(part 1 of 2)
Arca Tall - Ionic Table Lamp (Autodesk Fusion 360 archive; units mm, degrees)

design "Marble Base - Ionic Table Lamp - 120V" references "Balon v2", "Chinois", "Trove - TL", "Marble Base - Silicone Gasket", "Marble Base - Plastic Insert", "Rubber Grommet", "Neoprene Pad", "2-Pole Plug End", "Arca Tall", "T9 - Bulb", "Facet Petite", "T9-5In"
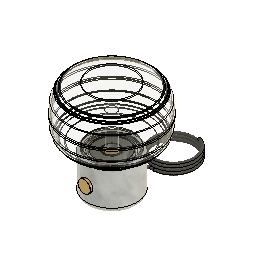
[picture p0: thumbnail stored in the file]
sketch "Sketch1" plane through (0, 0, 0) normal (0, 0, 1) x axis (1, 0, 0)
  circle C1 centre (0, 0) radius 63.5
  point P1 (0, 0)
  point P2 (0, 0)
  coincident P1 P2
extrude "Extrude1" new body sketch "Sketch1" along normal blind 101.6 bodies "Marble Base"
sketch "Sketch2" plane through (0, 0, 101.6) normal (0, 0, 1) x axis (-1, 0, 0)
  circle C1 centre (0, 0) radius 63.5
  circle C2 centre (0, 0) radius 53.975
  concentric C1 C2
  dimension "d3" diameter C2 = 107.95
extrude "Extrude2" cut sketch "Sketch2" profile of C2 against normal blind 34.925
sketch "Sketch3" plane through (0, 0, 66.675) normal (0, 0, 1) x axis (-1, 0, 0)
  circle C1 centre (0, 0) radius 53.975
  circle C2 centre (0, 0) radius 49.276
  point P1 (0, 0)
  point P3 (0, 0)
  coincident P1 P3
  dimension "d6" diameter C2 = 98.552
extrude "Extrude3" cut sketch "Sketch3" profile of C2 against normal blind 45.72
sketch "Sketch4" plane through (0, 0, 0) normal (0, 1, 0) x axis (1, 0, 0)
  circle C1 centre (0, -50.8) radius 3.81
  dimension "d9" diameter C1 = 7.62
extrude "Extrude4" cut sketch "Sketch4" against normal blind 127
sketch "Sketch5" plane through (0, 0, 0) normal (0, 1, 0) x axis (1, 0, 0)
  line L1 (0, -25.4) -> (0, 0)
  line L2 (0, -30.48) -> (0, -25.4)
  circle C1 centre (0, -30.48) radius 5.08
  point P1 (0, 0)
  point P2 (0, 0)
  point P4 (0, -30.48)
  point P5 (0, -30.48)
  coincident P1 P2
  vertical L1
  parallel L1 L2
  coincident P4 P5
  dimension "d12" diameter C1 = 10.16
extrude "Extrude5" cut sketch "Sketch5" profile of C1 along normal blind 114.3
fillet "Fillet1" radius 6.35 3.175 4.064
derived_base_feature "Derived Base Feature1" bodies "Rotary Switch"
derived_base_feature "Derived Base Feature1" bodies "Coiled - SVT (Blk Fabric)"
derived_base_feature "Derived Base Feature1" bodies "Glass Globe"
derived_base_feature "Derived Base Feature1" bodies "Metal Housing"
derived_base_feature "Derived Base Feature1" bodies "Metal Socket Cover"
derived_base_feature "Derived Base Feature1" bodies "Porcelain Socket"
derived_base_feature "Derived Base Feature1" bodies "Brass Dial - Dimmer Knob"
component_from_bodies "Body->Comp1"
offset_faces "OffsetFaces1" distance 12.7
offset_faces "OffsetFaces2" distance -12.7
derived_base_feature "Derived Base Feature1" bodies "Solitaire Petite"
move "Move1"
offset_faces "OffsetFaces1" distance 20.32
move "Move2"
extrude "Extrude6" add of existing geometry blind 25.4
offset_faces "OffsetFaces2" distance -3.81
fillet "Fillet2" radius 2.54
move "Move3"
derived_base_feature "Derived Base Feature2" bodies "Facet Petite"
move "Move4"
offset_faces "OffsetFaces1" distance 2.54
move "Move1"
derived_base_feature "Derived Base Feature1" bodies "Body1"
derived_base_feature "Derived Base Feature1" bodies "Body1"
derived_base_feature "Derived Base Feature1" bodies "Body1"
derived_base_feature "Derived Base Feature1" bodies "Body1"
derived_base_feature "Derived Base Feature1" bodies "Body1"
derived_base_feature "Derived Base Feature1" bodies "Body1", "Body2"
derived_base_feature "Derived Base Feature1" bodies "Body1"
position "Position1"
external_derived "ExternalDerived5" bodies "Plastic Insert"
derived_instance "DerivedInstance15"
offset_faces "OffsetFaces1" distance 3.81
offset_faces "OffsetFaces2" distance -1.0414
move "Move6"
external_derived "ExternalDerived6" sketch "Sketch3" bodies "Silicone Gasket"
derived_instance "DerivedInstance16"
offset_faces "OffsetFaces3" distance -10.795
move "Move1"
move_face "MoveFace1"
position "Position2"
position "Position3"
position "Position4"
position "Position5"
move "Move2"
position "Position6"
offset_faces "OffsetFaces2" distance -7.62
chamfer "Chamfer1" distance 0.381
remove_instance "RemoveInstance1"
remove_instance "RemoveInstance2"
remove_instance "RemoveInstance3"
remove_instance "RemoveInstance4"
move "Move1"
derived_base_feature "Derived Base Feature5" bodies "Oculo Petite"
align "Align1"
external_derived "ExternalDerived8"
derived_base_feature "Derived Base Feature7" bodies "Balon v2"
derived_base_feature "Derived Base Feature8" bodies "Balon v3"
align "Align3"
align "Align4"
external_derived "ExternalDerived10"
component_insert "Component Insert1"
position "Position7"
position "Position8"
derived_base_feature "Derived Base Feature11" bodies "Trove - TL"
move "Move10"
move "Move11"
remove_instance "RemoveInstance5"
split "Split1" bodies "Trove - TL (1)"
remove_body "RemoveBody2"
remove_body "RemoveBody3"
external_derived "ExternalDerived13" bodies "Trove - TL"
derived_instance "DerivedInstance20"
remove_body "RemoveBody4"
remove_body "RemoveBody5"
component_insert "Component Insert2"
component_insert "Component Insert3"
component_from_bodies "Body->Comp2"
remove_body "RemoveBody7"
move "Move12"
move "Move13"
sketch "Sketch6" plane through (0, 0, 97.917) normal (0, 0, 1) x axis (-1, 0, 0)
  circle C1 centre (0, 0) radius 41.275
  circle C2 centre (0, 0) radius 19.685
  arc A1 centre (0, 0) radius 29.3982 clockwise from (-27.6283, 10.0466) to (27.6283, 10.0466)
  arc A2 centre (0, 0) radius 26.2232 clockwise from (-24.6444, 8.9616) to (24.6444, 8.9616)
  arc A3 centre (0, 0) radius 32.5732 clockwise from (-30.6121, 11.1317) to (30.6121, 11.1317)
  arc A4 centre (0, 0) radius 35.7482 clockwise from (-33.596, 12.2167) to (33.596, 12.2167)
  point P1 (0, 0)
  point P3 (0, 0)
  coincident P1 P3
  dimension "d37" = -3.175
  dimension "d38" = 3.175
  dimension "d39" = 6.35
  dimension "d40" Text1-Height = 2.54
  dimension "d41" Text2-Height = 2.54
  dimension "d42" Text3-Height = 2.54
  dimension "d43" Text4-Height = 2.54
extrude "Extrude1" cut sketch "Sketch6" against normal blind 0.254
external_derived "ExternalDerived14" bodies "Rubber Grommet"
derived_instance "DerivedInstance19"
external_derived "ExternalDerived15" bodies "2-Pole Plug End"
derived_instance "DerivedInstance18"
external_derived "ExternalDerived16" bodies "Neoprene Pad"
derived_instance "DerivedInstance17"
position "Position9"
position "Position10"
position "Position11"
position "Position12"
external_derived "ExternalDerived17" bodies "Chinois"
derived_instance "DerivedInstance21"
position "Position13"
move "Move3"
remove_body "RemoveBody8"
component_insert "Component Insert4"
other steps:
derived_base_feature "Derived Base Feature1" bodies "Trove - TL"
derived_base_feature "Derived Base Feature1" bodies "Chinois"
derived_base_feature "Derived Base Feature1" bodies "Rubber Grommet"
derived_base_feature "Derived Base Feature1" bodies "2-Pole Plug End"
derived_base_feature "Derived Base Feature1" bodies "Neoprene Pad"
move "Move1"
base_feature "Base Feature1" bodies "Oculo Petite", "Arca Petite"
derived_base_feature "Derived Base Feature1" bodies "Plastic Insert"
derived_base_feature "Derived Base Feature1" bodies "Silicone Gasket"
base_feature "Base Feature1" bodies "Marble Base"
move "Move8"
derived_base_feature "Derived Base Feature"
create_component "CreateComponent1"
create_component "CreateComponent2"
create_component "CreateComponent3"
create_component "CreateComponent4"
create_component "CreateComponent5"
create_component "CreateComponent6"
create_component "CreateComponent7"
create_component "CreateComponent8"
remove_body "RemoveBody1"
create_component "CreateComponent9"
create_component "CreateComponent10"
create_component "CreateComponent11"
create_component "CreateComponent12"
create_component "CreateComponent13"
create_component "CreateComponent14"
create_component "CreateComponent15"
create_component "CreateComponent16"
create_component "CreateComponent17"
create_component "CreateComponent18"
remove_body "RemoveBody6"
create_component "CreateComponent19"
create_component "CreateComponent20"
create_component "CreateComponent21"
create_component "CreateComponent22"
create_component "CreateComponent23"
named bodies: "Marble Base", "Rotary Switch", "Coiled - SVT (Blk Fabric)", "Glass Globe", "Metal Housing", "Metal Socket Cover", "Porcelain Socket", "Brass Dial - Dimmer Knob", "Solitaire Petite", "Facet Petite", "Body1", "Body2", "Plastic Insert", "Silicone Gasket", "Oculo Petite", "Balon v2", "Balon v3", "Trove - TL", "Trove - TL (1)", "Arca Petite", "Neoprene Pad", "2-Pole Plug End", "Rubber Grommet", "Chinois"

design "Neoprene Pad"
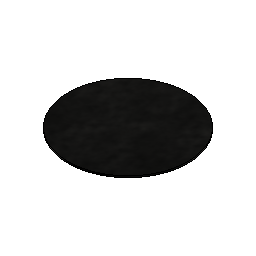
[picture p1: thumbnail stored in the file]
sketch "Sketch1" plane through (0, 0, 0) normal (0, 0, 1) x axis (1, 0, 0)
  circle C1 centre (0, 0) radius 57.15
  point P1 (0, 0)
  point P2 (0, 0)
  coincident P1 P2
extrude "Extrude1" new body sketch "Sketch1" along normal blind 1.5875 bodies "Neoprene Pad"
component_from_bodies "Body->Comp"
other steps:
base_feature "Base Feature" bodies "Neoprene Pad"
create_component "CreateComponent1"
remove_body "RemoveBody1"
named bodies: "Neoprene Pad"

design "T9 - Bulb"
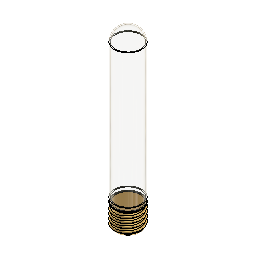
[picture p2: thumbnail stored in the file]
sketch "Sketch1" plane through (0, 0, 0) normal (0, 1, 0) x axis (1, 0, 0)
  line L1 (0, -166.37) -> (0, 0)
  line L2 (13.97, -13.97) -> (13.97, -152.4)
  line L3 (-13.97, -152.4) -> (-13.97, -13.97)
  line L4 (0, 0) -> (0, -166.37)
  line L5 (12.97, -13.97) -> (12.97, -152.4)
  line L6 (-12.97, -152.4) -> (-12.97, -13.97)
  line L7 (-12.3978, -10.16) -> (-13.4404, -10.16)
  line L8 (13.4404, -10.16) -> (12.3978, -10.16)
  arc A1 centre (0, -152.4) radius 13.97 clockwise from (13.97, -152.4) to (-13.97, -152.4)
  arc A2 centre (0, -152.4) radius 12.97 clockwise from (12.97, -152.4) to (-12.97, -152.4)
  arc A3 centre (0, -13.97) radius 13.97 clockwise from (13.4404, -10.16) to (13.97, -13.97)
  arc A4 centre (0, -13.97) radius 13.97 clockwise from (-13.97, -13.97) to (-13.4404, -10.16)
  arc A5 centre (0, -13.97) radius 12.97 clockwise from (12.3978, -10.16) to (12.97, -13.97)
  arc A6 centre (0, -13.97) radius 12.97 clockwise from (-12.97, -13.97) to (-12.3978, -10.16)
  point P1 (0, 0)
  point P2 (0, 0)
  point P3 (0, -166.37)
  point P10 (0, 0)
  point P17 (13.4404, -10.16)
  point P19 (12.3978, -10.16)
  point P4 (13.97, -152.4)
  point P5 (13.97, -13.97)
  coincident P1 P2
  vertical L1
  tangent L2 A3
  tangent L3 A3
  parallel L2 L3
  tangent L3 A1
  tangent L2 A1
  midpoint P3 A1
  coincident P1 P10
  perpendicular L1 L7
  coincident P17 L7
  concentric A3 A4
  coincident P10 A3
  concentric A1 A2
  tangent L5 A2
  tangent L5 A5
  tangent L6 A5
  tangent L6 A2
  coincident P19 L7
  concentric A5 A6
  collinear L7 L8
  dimension "d6" distance L2 L3 = 27.94
  dimension "d7" distance P4 P5 = 138.43
revolve "Revolve1" sketch "Sketch1" AlongAngle 360 bodies "T9"
derived_base_feature "Derived Base Feature" bodies "E26 Base"
align "Align1"
move "Move1"
component_from_bodies "Body->Comp1"
component_from_bodies "Body->Comp2"
copy_paste "CutPaste1"
copy_paste "CutPaste2"
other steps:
base_feature "Base Feature1" bodies "T9"
base_feature "Base Feature1" bodies "E26 Base"
create_component "CreateComponent1"
create_component "CreateComponent2"
remove_body "RemoveBody1"
create_component "CreateComponent3"
remove_body "RemoveBody2"
remove_instance "RemoveInstance1"
remove_instance "RemoveInstance2"
named bodies: "T9", "E26 Base"

design "Marble Base - Silicone Gasket"
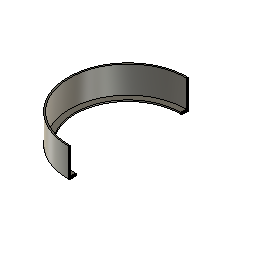
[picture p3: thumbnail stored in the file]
sketch "Sketch1" plane through (0, 0, 0) normal (0, 0, 1) x axis (1, 0, 0)
  circle C1 centre (0, 0) radius 53.34
  point P1 (0, 0)
  point P2 (0, 0)
  coincident P1 P2
extrude "Extrude1" new body sketch "Sketch1" along normal blind 25.4 bodies "Silicone Gasket"
shell "Shell1" innerThickness 1.27
sketch "Sketch2" plane through (0, 0, 1.27) normal (0, 0, 1) x axis (-1, 0, 0)
  circle C1 centre (0, 0) radius 52.07
  circle C2 centre (0, 0) radius 46.99
  concentric C1 C2
extrude "Extrude2" cut sketch "Sketch2" profile of C2 against normal blind 12.7
component_from_bodies "Body->Comp"
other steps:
base_feature "Base Feature" bodies "Silicone Gasket"
create_component "CreateComponent1"
remove_body "RemoveBody1"
named bodies: "Silicone Gasket"

design "2-Pole Plug End"
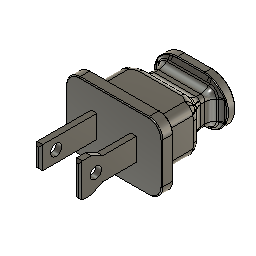
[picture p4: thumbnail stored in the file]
sketch "Sketch1" plane through (0, 0, 0) normal (0, 1, 0) x axis (1, 0, 0)
  line L1 (9.6837, 9.525) -> (-9.6837, 9.525)
  line L2 (13.4938, -5.715) -> (13.4938, 5.715)
  line L3 (-9.6837, -9.525) -> (9.6837, -9.525)
  line L4 (-13.4937, 5.715) -> (-13.4937, -5.715)
  line L5 (13.4938, -9.525) -> (-13.4937, 9.525)
  line L6 (-13.4937, -9.525) -> (13.4938, 9.525)
  arc A1 centre (-9.6837, -5.715) radius 3.81 clockwise from (-9.6837, -9.525) to (-13.4937, -5.715)
  arc A2 centre (9.6837, -5.715) radius 3.81 clockwise from (13.4938, -5.715) to (9.6837, -9.525)
  arc A3 centre (9.6837, 5.715) radius 3.81 clockwise from (9.6837, 9.525) to (13.4938, 5.715)
  arc A4 centre (-9.6837, 5.715) radius 3.81 clockwise from (-13.4937, 5.715) to (-9.6837, 9.525)
  point P6 (0, 0)
  point P1 (0, 0)
  point P5 (-13.4937, -9.525)
  point P4 (13.4938, -9.525)
  point P3 (13.4938, 9.525)
  point P2 (-13.4937, 9.525)
  horizontal L1
  perpendicular L1 L2
  parallel L1 L3
  parallel L2 L4
  coincident L5 P6
  coincident L6 P6
  coincident P1 P6
  coincident P5 L4
  coincident P5 L3
  tangent L4 A1
  tangent L3 A1
  coincident P4 L3
  coincident P4 L2
  tangent L3 A2
  tangent L2 A2
  equal A1 A2
  coincident P3 L2
  coincident P3 L1
  tangent L2 A3
  tangent L1 A3
  equal A1 A3
  coincident P2 L1
  coincident P2 L4
  tangent L1 A4
  tangent L4 A4
  equal A1 A4
  dimension "d1" distance P4 P5 = 26.9875
  dimension "d2" distance P2 P5 = 19.05
  dimension "d3" radius A1 = 3.81
extrude "Extrude1" new body sketch "Sketch1" profile of L1 L2 L3 L4 A1 A2 A3 A4 along normal blind 3.175
sketch "Sketch2" plane through (0, 3.175, 0) normal (0, 1, 0) x axis (-1, 0, 0)
  line L1 (9.6837, -9.525) -> (-9.6837, -9.525)
  line L2 (13.4937, 5.715) -> (13.4937, -5.715)
  line L3 (-9.6837, 9.525) -> (9.6837, 9.525)
  line L4 (-13.4938, -5.715) -> (-13.4938, 5.715)
  line L5 (10.16, -6.35) -> (-10.16, -6.35)
  line L6 (10.16, 6.35) -> (10.16, -6.35)
  line L7 (-10.16, 6.35) -> (10.16, 6.35)
  line L8 (-10.16, -6.35) -> (-10.16, 6.35)
  line L9 (10.16, 6.35) -> (-10.16, -6.35)
  line L10 (-10.16, 6.35) -> (10.16, -6.35)
  arc A1 centre (-9.6837, -5.715) radius 3.81 clockwise from (-9.6837, -9.525) to (-13.4938, -5.715)
  arc A2 centre (9.6837, -5.715) radius 3.81 clockwise from (13.4937, -5.715) to (9.6837, -9.525)
  arc A3 centre (9.6837, 5.715) radius 3.81 clockwise from (9.6837, 9.525) to (13.4937, 5.715)
  arc A4 centre (-9.6837, 5.715) radius 3.81 clockwise from (-13.4938, 5.715) to (-9.6837, 9.525)
  point P18 (0, 0)
  point P1 (0, 0)
  horizontal L5
  perpendicular L5 L6
  parallel L5 L7
  parallel L6 L8
  coincident L9 P18
  coincident L10 P18
  coincident P1 P18
extrude "Extrude2" add sketch "Sketch2" profile of L5 L6 L7 L8 along normal blind 9.525
sketch "Sketch3" plane through (0, 12.7, 0) normal (0, 1, 0) x axis (-1, 0, 0)
  line L1 (-10.16, -6.35) -> (-10.16, 6.35)
  line L2 (10.16, -6.35) -> (-10.16, -6.35)
  line L3 (10.16, 6.35) -> (10.16, -6.35)
  line L4 (-10.16, 6.35) -> (10.16, 6.35)
  line L5 (-7.1437, 3.9688) -> (7.1437, 3.9688)
  line L6 (-7.1437, -3.9688) -> (-7.1437, 3.9688)
  line L7 (7.1437, -3.9688) -> (-7.1437, -3.9688)
  line L8 (7.1437, 3.9688) -> (7.1437, -3.9688)
  line L9 (-7.1437, -3.9688) -> (7.1437, 3.9688)
  line L10 (7.1437, -3.9688) -> (-7.1437, 3.9688)
  point P10 (0, 0)
  point P1 (0, 0)
  point P8 (-7.1437, -3.9688)
  point P9 (7.1437, -3.9688)
  point P7 (-7.1437, 3.9688)
  horizontal L5
  perpendicular L5 L6
  parallel L5 L7
  parallel L6 L8
  coincident L9 P10
  coincident L10 P10
  coincident P1 P10
  dimension "d8" distance P8 P9 = 14.2875
  dimension "d9" distance P7 P8 = 7.9375
extrude "Extrude3" add sketch "Sketch3" profile of L5 L6 L7 L8 along normal blind 11.1125
fillet "Fillet1" radius 2.286 1.27 0.254
chamfer "Chamfer1" distance 3.429
fillet "Fillet2" radius 2.54 1.905
sketch "Sketch4" plane through (0, 23.8125, 0) normal (0, 1, 0) x axis (-1, 0, 0)
  line L1 (-7.1437, -2.6987) -> (-7.1437, 2.6987)
  line L2 (5.8737, -3.9688) -> (-5.8737, -3.9688)
  line L3 (7.1437, 2.6987) -> (7.1437, -2.6987)
  line L4 (-5.8737, 3.9688) -> (5.8737, 3.9688)
  line L5 (-3.81, 6.604) -> (3.81, 6.604)
  line L6 (3.81, -6.604) -> (-3.81, -6.604)
  line L7 (-10.414, 0) -> (10.414, 0)
  arc A1 centre (-5.8737, 2.6987) radius 1.27 clockwise from (-7.1437, 2.6987) to (-5.8737, 3.9688)
  arc A2 centre (-5.8737, -2.6987) radius 1.27 clockwise from (-5.8737, -3.9688) to (-7.1437, -2.6987)
  arc A3 centre (5.8737, -2.6987) radius 1.27 clockwise from (7.1437, -2.6987) to (5.8737, -3.9688)
  arc A4 centre (5.8737, 2.6987) radius 1.27 clockwise from (5.8737, 3.9688) to (7.1437, 2.6987)
  arc A5 centre (-3.81, 0) radius 6.604 clockwise from (-3.81, -6.604) to (-3.81, 6.604)
  arc A6 centre (3.81, 0) radius 6.604 clockwise from (3.81, 6.604) to (3.81, -6.604)
  point P20 (10.414, 0)
  point P21 (-10.414, 0)
  tangent L5 A5
  tangent A5 L6
  parallel L5 L6
  tangent L6 A6
  tangent L5 A6
  midpoint A6 P20
  midpoint A5 P21
  perpendicular L1 L7
extrude "Extrude4" add sketch "Sketch4" profile of A1 L1 A2 L2 A3 L3 A4 L4 L5 A5 L6 A6 against normal blind 2.286
chamfer "Chamfer2" distance 1.778
fillet "Fillet3" radius 1.778
fillet "Fillet4" radius 0.254
fillet "Fillet5" radius 0.254
fillet "Fillet6" radius 0.254
fillet "Fillet7" radius 3.175
sketch "Sketch5" plane through (0, 0, 0) normal (0, -1, 0) x axis (1, 0, 0)
  line L1 (-13.2397, -5.715) -> (-13.2397, 5.715)
  line L2 (9.6837, -9.271) -> (-9.6837, -9.271)
  line L3 (13.2397, 5.715) -> (13.2397, -5.715)
  line L4 (-9.6837, 9.271) -> (9.6837, 9.271)
  line L5 (-6.35, -3.175) -> (-6.35, 3.175)
  line L6 (6.35, 3.175) -> (-6.35, -3.175)
  line L7 (-6.35, 3.175) -> (6.35, -3.175)
  line L8 (-4.7625, 3.175) -> (-6.35, 3.175)
  line L9 (-4.7625, -3.175) -> (-4.7625, 3.175)
  line L10 (-6.35, -3.175) -> (-4.7625, -3.175)
  line L11 (-6.35, 3.175) -> (-6.35, -3.175)
  line L12 (0, -3.302) -> (0, 3.81)
  line L13 (4.7625, -3.175) -> (4.7625, 3.175)
  line L14 (4.7625, 3.175) -> (6.35, 3.175)
  line L15 (6.35, -3.175) -> (6.35, 3.175)
  line L16 (6.35, -3.175) -> (4.7625, -3.175)
  arc A1 centre (-9.6837, 5.715) radius 3.556 clockwise from (-13.2397, 5.715) to (-9.6837, 9.271)
  arc A2 centre (-9.6837, -5.715) radius 3.556 clockwise from (-9.6837, -9.271) to (-13.2397, -5.715)
  arc A3 centre (9.6837, -5.715) radius 3.556 clockwise from (13.2397, -5.715) to (9.6837, -9.271)
  arc A4 centre (9.6837, 5.715) radius 3.556 clockwise from (9.6837, 9.271) to (13.2397, 5.715)
  point P18 (0, 0)
  point P1 (0, 0)
  point P14 (-6.35, -3.175)
  point P27 (6.35, -3.175)
  point P17 (-6.35, 3.175)
  point P26 (6.35, 3.175)
  point P19 (-4.7625, 3.175)
  point P24 (4.7625, 3.175)
  point P20 (-4.7625, -3.175)
  point P25 (4.7625, -3.175)
  point P21 (-6.35, -3.175)
  point P28 (6.35, -3.175)
  point P15 (6.35, -3.175)
  point P16 (6.35, 3.175)
  coincident L6 P18
  coincident L7 P18
  coincident P1 P18
  horizontal L8
  vertical L9
  horizontal L10
  vertical L11
  vertical L12
  symmetric P14 L12 P27
  symmetric P17 L12 P26
  symmetric P19 L12 P24
  symmetric P20 L12 P25
  symmetric P21 L12 P28
  dimension "d36" distance P15 P16 = 6.35
  dimension "d37" distance P17 P19 = 1.5875
extrude "Extrude5" add sketch "Sketch5" profile of L5 L8 L9 L10 L11 L13 L14 L15 L16 along normal blind 15.875
sketch "Sketch7" plane through (0, 0, 3.175) normal (0, 0, 1) x axis (-1, 0, 0)
  line L1 (-4.7625, 0) -> (-6.35, 0)
  line L2 (-4.7625, 15.875) -> (-4.7625, 0)
  line L3 (-6.35, 15.875) -> (-4.7625, 15.875)
  line L4 (-6.35, 0) -> (-6.35, 15.875)
  line L5 (-4.7625, 15.875) -> (-6.35, 15.875)
  line L6 (-4.7625, 9.525) -> (-4.7625, 15.875)
  line L7 (-6.35, 9.525) -> (-4.7625, 9.525)
  line L8 (-6.35, 15.875) -> (-6.35, 9.525)
  point P5 (-6.35, 15.875)
  point P6 (-6.35, 15.875)
  point P9 (-6.35, 9.525)
  horizontal L5
  vertical L6
  horizontal L7
  vertical L8
  coincident P5 P6
  dimension "d45" distance P6 P9 = 6.35
extrude "Extrude7" add sketch "Sketch7" profile of L2 L3 L4 L5 L6 L7 L8 against normal blind 7.9375 and along normal blind 1.5875
chamfer "Chamfer3" distance 0.508
chamfer "Chamfer4" distance 0.635 distance 0.635
sketch "Sketch6" plane through (6.35, 0, 0) normal (1, 0, 0) x axis (0, 1, 0)
  line L1 (0, -3.175) -> (-9.525, -3.175)
  line L2 (0, 3.175) -> (0, -3.175)
  line L3 (-9.525, 3.175) -> (0, 3.175)
  line L4 (-15.367, -4.6355) -> (-15.367, 4.6355)
  line L5 (-11.43, 0) -> (-16.002, 0)
  line L6 (-9.525, -4.7625) -> (-15.24, -4.7625)
  line L7 (-9.525, -3.175) -> (-9.525, -4.7625)
  line L8 (-9.525, 4.7625) -> (-9.525, 3.175)
  line L9 (-15.24, 4.7625) -> (-9.525, 4.7625)
  line L10 (-15.24, -4.7625) -> (-15.367, -4.6355)
  line L11 (-15.367, 4.6355) -> (-15.24, 4.7625)
  circle C1 centre (-11.43, 0) radius 1.5875
  point P9 (-11.43, 0)
  point P10 (-11.43, 0)
  perpendicular L4 L5
  coincident P9 P10
  dimension "d42" diameter C1 = 3.175
extrude "Extrude6" cut sketch "Sketch6" profile of C1 against normal blind 20.32
chamfer "Chamfer5" distance 3.175 distance 1.5875 distance 3.175 distance 1.5875
component_from_bodies "Body->Comp"
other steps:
base_feature "Base Feature" bodies "2-Pole Plug End"
create_component "CreateComponent1"
remove_body "RemoveBody1"
named bodies: "2-Pole Plug End"

design "Facet Petite"
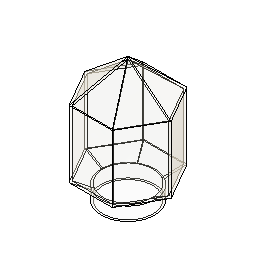
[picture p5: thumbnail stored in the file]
sketch "Sketch7" plane through (0, 0, 0) normal (1, 0, 0) x axis (0, 1, 0)
sketch "Sketch8" plane through (0, 0, 0) normal (0, 0, 1) x axis (1, 0, 0)
  circle C1 centre (0, 0) radius 50.8
  point P1 (0, 0)
  point P2 (0, 0)
  coincident P1 P2
  dimension "d17" diameter C1 = 101.6
extrude "Extrude5" new body sketch "Sketch8" along normal blind 25.4 and against normal blind 25.4
work_plane "WorkPlane1" AlongDistance 17.78
sketch "Sketch10" plane through (0, 0, 25.4) normal (0, 0, 1) x axis (-1, 0, 0)
  circle C1 centre (0, 0) radius 50.8
sketch "Sketch12" plane through (0, 0, 43.18) normal (0, 0, 1) x axis (1, 0, 0)
  line L1 (-82.1223, 0) -> (-41.0612, 71.12)
  line L2 (-41.0612, -71.12) -> (-82.1223, 0)
  line L3 (41.0612, -71.12) -> (-41.0612, -71.12)
  line L4 (82.1223, 0) -> (41.0612, -71.12)
  line L5 (41.0612, 71.12) -> (82.1223, 0)
  line L6 (-41.0612, 71.12) -> (41.0612, 71.12)
  point P1 (0, 0)
  point P8 (0, 0)
  coincident P1 P8
  dimension "d22" distance P8 L6 = 71.12
sketch "Sketch15" plane through (0, 0, 0) normal (0, 1, 0) x axis (1, 0, 0)
  line L1 (53.7365, -21.6801) -> (82.1223, -43.18)
  line L2 (-50.8, -25.4) -> (-82.1223, -43.18)
  point P2 (82.1223, -43.18)
  point P3 (82.1223, -43.18)
  point P5 (-82.1223, -43.18)
  point P7 (-82.1223, -43.18)
  point P6 (-50.8, -25.4)
  point P8 (-50.8, -25.4)
  coincident P2 P3
  coincident P5 P7
  coincident P6 P8
sketch "Sketch17" plane through (0, 0, 25.4) normal (0, 0, 1) x axis (-1, 0, 0)
  line L1 (51.3255, 0) -> (0, 0)
  line L2 (73.3235, 0) -> (0, 0)
  line L3 (-41.0612, -71.12) -> (-25.4, -43.9941)
  line L4 (-36.6617, -63.5) -> (-25.4, -43.9941)
  line L5 (78.4305, 0) -> (0, 0)
  line L6 (41.0612, -71.12) -> (25.4, -43.9941)
  line L7 (25.4, 43.9941) -> (41.0612, 71.12)
  line L8 (73.3235, 0) -> (0, 0)
  line L9 (-25.4, 43.9941) -> (-41.0612, 71.12)
  line L10 (0, 0) -> (0, 0)
  circle C1 centre (0, 0) radius 50.8
  point P1 (0, 0)
  point P4 (0, 0)
  point P2 (-41.0612, -71.12)
  point P6 (-41.0612, -71.12)
  point P3 (0, 0)
  point P7 (0, 0)
  point P9 (-25.4, -43.9941)
  point P12 (41.0612, -71.12)
  point P13 (41.0612, -71.12)
  point P15 (25.4, -43.9941)
  point P16 (41.0612, 71.12)
  point P17 (41.0612, 71.12)
  point P18 (25.4, 43.9941)
  point P19 (-41.0612, 71.12)
  point P20 (-41.0612, 71.12)
  point P21 (0, 0)
  point P23 (-25.4, 43.9941)
  point P25 (0, 0)
  point P24 (0, 0)
  point P26 (0, 0)
  horizontal L1
  coincident P1 P4
  coincident P2 P6
  horizontal L2
  coincident P3 P7
  coincident C1 P9
  coincident P12 P13
  horizontal L5
  coincident C1 P15
  coincident P16 P17
  coincident C1 P18
  coincident P19 P20
  horizontal L8
  coincident P1 P21
  coincident C1 P23
  coincident P1 P25
  coincident P24 P26
extrude "Extrude6" new body sketch "Sketch12" along normal blind 127
work_plane "WorkPlane2" AlongDistance 66.04
sketch "Sketch18" plane through (0, 0, 236.22) normal (0, 0, 1) x axis (1, 0, 0)
  line L1 (41.0612, -71.12) -> (0, 0)
  line L2 (82.1223, 0) -> (0, 0)
  line L3 (41.0612, 71.12) -> (0, 0)
  line L4 (-41.0612, 71.12) -> (0, 0)
  line L5 (-82.1223, 0) -> (0, 0)
  line L6 (-41.0612, -71.12) -> (0, 0)
  point P1 (0, 0)
  point P3 (0, 0)
  point P2 (41.0612, -71.12)
  point P4 (41.0612, -71.12)
  point P6 (0, 0)
  point P5 (82.1223, 0)
  point P7 (82.1223, 0)
  point P9 (0, 0)
  point P8 (41.0612, 71.12)
  point P10 (41.0612, 71.12)
  point P12 (0, 0)
  point P11 (-41.0612, 71.12)
  point P13 (-41.0612, 71.12)
  point P15 (0, 0)
  point P14 (-82.1223, 0)
  point P16 (-82.1223, 0)
  point P18 (0, 0)
  point P17 (-41.0612, -71.12)
  point P19 (-41.0612, -71.12)
  coincident P1 P3
  coincident P2 P4
  coincident P1 P6
  coincident P5 P7
  coincident P1 P9
  coincident P8 P10
  coincident P1 P12
  coincident P11 P13
  coincident P1 P15
  coincident P14 P16
  coincident P1 P18
  coincident P17 P19
loft "Loft1"
loft "Loft2" sketch "Sketch17"
component_from_bodies "Body->Comp"
extrude "Extrude1" cut of existing geometry blind -25.4
shell "Shell2" innerThickness 3.81
fillet "Fillet1" radius 7.62
fillet "Fillet2" radius 6.35
fillet "Fillet3" radius 6.35
fillet "Fillet4" radius 6.35
fillet "Fillet5" radius 6.35
fillet "Fillet6" radius 6.35
fillet "Fillet7" radius 3.81
fillet "Fillet8" radius 6.35
fillet "Fillet9" radius 6.35
fillet "Fillet10" radius 6.35
fillet "Fillet11" radius 6.35
fillet "Fillet12" radius 6.35
fillet "Fillet13" radius 2.286
shell "Shell1" innerThickness 2.54
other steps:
base_feature "Base Feature"
create_component "CreateComponent3"
remove_body "RemoveBody2"

design "Chinois"
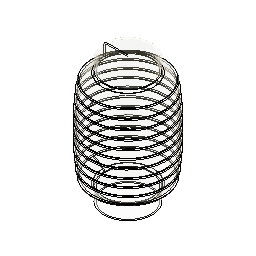
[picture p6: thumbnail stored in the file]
named bodies: "Chinois"

design "Marble Base - Plastic Insert"
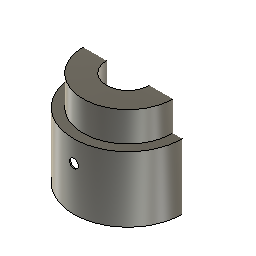
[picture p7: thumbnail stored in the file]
sketch "Sketch1" plane through (0, 0, 0) normal (0, 0, 1) x axis (1, 0, 0)
  circle C1 centre (0, 0) radius 50.038
  point P1 (0, 0)
  point P2 (0, 0)
  coincident P1 P2
  dimension "d1" diameter C1 = 100.076
extrude "Extrude1" new body sketch "Sketch1" along normal blind 72.898 bodies "Plastic Insert"
shell "Shell1" innerThickness 1.016
work_plane "WorkPlane1" AlongDistance 18.034
sketch "Sketch2" plane through (0, 0, 90.932) normal (0, 0, 1) x axis (1, 0, 0)
  circle C1 centre (0, 0) radius 20.701
  point P1 (0, 0)
  point P2 (0, 0)
  coincident P1 P2
  dimension "d6" diameter C1 = 41.402
extrude "Extrude2" add sketch "Sketch2" against normal blind 65.024
shell "Shell2" innerThickness 1.016
sketch "Sketch3" plane through (0, 0, 0) normal (0, 1, 0) x axis (1, 0, 0)
  line L1 (5.08, -20.32) -> (-5.08, -20.32)
  line L2 (5.08, 20.32) -> (5.08, -20.32)
  line L3 (-5.08, 20.32) -> (5.08, 20.32)
  line L4 (-5.08, -20.32) -> (-5.08, 20.32)
  line L5 (5.08, 20.32) -> (-5.08, -20.32)
  line L6 (-5.08, 20.32) -> (5.08, -20.32)
  point P6 (0, 0)
  point P1 (0, 0)
  horizontal L1
  perpendicular L1 L2
  parallel L1 L3
  parallel L2 L4
  coincident L5 P6
  coincident L6 P6
  coincident P1 P6
extrude "Extrude3" cut sketch "Sketch3" profile of L1 L2 L3 L4 along normal blind 91.44
sketch "Sketch4" plane through (0, 0, 0) normal (0, 1, 0) x axis (1, 0, 0)
  line L1 (0, -40.64) -> (0, 0)
  circle C1 centre (0, -40.64) radius 4.064
  point P1 (0, 0)
  point P2 (0, 0)
  point P3 (0, -40.64)
  point P4 (0, -40.64)
  coincident P1 P2
  vertical L1
  coincident P3 P4
  dimension "d12" diameter C1 = 8.128
work_plane "WorkPlane2" AlongDistance -91.44
sketch "Sketch5" plane through (0, -91.44, 0) normal (0, 1, 0) x axis (1, 0, 0)
  circle C1 centre (0, -40.64) radius 4.064
extrude "Extrude4" cut sketch "Sketch5" along normal blind 63.5
sketch "Sketch6" plane through (0, 0, 26.924) normal (0, 0, 1) x axis (-1, 0, 0)
  circle C1 centre (0, 0) radius 19.685
  circle C2 centre (0, 0) radius 5.461
  concentric C1 C2
  dimension "d16" diameter C2 = 10.922
extrude "Extrude5" cut sketch "Sketch6" profile of C2 against normal blind 15.24
sketch "Sketch7" plane through (0, 0, 72.898) normal (0, 0, 1) x axis (-1, 0, 0)
  circle C1 centre (0, 0) radius 20.701
  circle C2 centre (0, 0) radius 50.038
  circle C3 centre (0, 0) radius 20.701
  circle C4 centre (0, 0) radius 45.72
  point P1 (0, 0)
  point P3 (0, 0)
  point P4 (0, 0)
  coincident P1 P3
  coincident P1 P4
extrude "Extrude6" add sketch "Sketch7" profile of C1 C3 C4 along normal blind 18.034
sketch "Sketch8" plane through (0, 0, 71.882) normal (0, 0, -1) x axis (1, 0, 0)
  circle C1 centre (0, 0) radius 20.701
  circle C2 centre (0, 0) radius 49.022
  circle C3 centre (0, 0) radius 20.701
  circle C4 centre (0, 0) radius 44.704
  point P1 (0, 0)
  point P3 (0, 0)
  point P4 (0, 0)
  coincident P1 P3
  coincident P1 P4
  dimension "d21" diameter C4 = 89.408
extrude "Extrude7" cut sketch "Sketch8" profile of C1 C3 C4 against normal blind 17.78
extrude "Extrude8" add of existing geometry blind 9.398
extrude "Extrude9" cut of existing geometry blind -9.398
component_from_bodies "Body->Comp"
offset_faces "OffsetFaces1" distance 4.445
offset_faces "OffsetFaces2" distance -4.445
offset_faces "OffsetFaces3" distance 3.175
offset_faces "OffsetFaces4" distance 3.175
offset_faces "OffsetFaces5" distance 3.175
offset_faces "OffsetFaces6" distance -3.175
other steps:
base_feature "Base Feature" bodies "Plastic Insert"
create_component "CreateComponent1"
remove_body "RemoveBody1"
named bodies: "Plastic Insert"

design "Arca Tall"
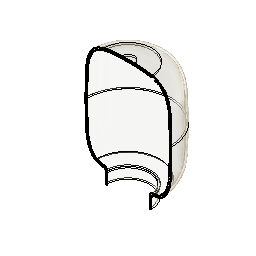
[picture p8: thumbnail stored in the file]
derived_base_feature "Derived Base Feature" bodies "Balon"
work_plane "WorkPlane1" AlongDistance 0
sketch "Sketch1" plane through (0, 0, 0) normal (0, 1, 0) x axis (1, 0, 0)
  line L1 (0, 317.5) -> (0, 2.9083)
  curve K1 (-82.9821, 124.2212) -> (-50.8, 237.8015)
  curve K2 (-51.0925, 237.681) -> (-50.8, 237.8015)
  curve K3 (-51.3855, 237.5558) -> (-51.0925, 237.681)
  curve K4 (-54.7608, 236.0513) -> (-51.3855, 237.5558)
  curve K5 (-57.9615, 234.05) -> (-54.7608, 236.0513)
  curve K6 (-67.2727, 226.749) -> (-57.9615, 234.05)
  curve K7 (-69.0552, 224.2615) -> (-67.2727, 226.749)
  curve K8 (-72.1872, 218.7832) -> (-69.0552, 224.2615)
  curve K9 (-74.1213, 215.1556) -> (-72.1872, 218.7832)
  curve K10 (-78.3031, 204.3965) -> (-74.1213, 215.1556)
  curve K11 (-79.7275, 197.3397) -> (-78.3031, 204.3965)
  curve K12 (-81.3333, 185.4664) -> (-79.7275, 197.3397)
  curve K13 (-81.6254, 178.4008) -> (-81.3333, 185.4664)
  curve K14 (-82.49, 152.2133) -> (-81.6254, 178.4008)
  curve K15 (-82.9821, 136.067) -> (-82.49, 152.2133)
  curve K16 (-82.9821, 124.2212) -> (-82.9821, 136.067)
  curve K17 (50.8, 237.7999) -> (82.9821, 124.2212)
  curve K18 (82.9821, 140.3031) -> (82.9821, 124.2212)
  curve K19 (81.9353, 169.4257) -> (82.9821, 140.3031)
  curve K20 (81.3621, 183.6489) -> (81.9353, 169.4257)
  curve K21 (80.9478, 189.8724) -> (81.3621, 183.6489)
  curve K22 (77.8147, 206.9858) -> (80.9478, 189.8724)
  curve K23 (74.9652, 213.2153) -> (77.8147, 206.9858)
  curve K24 (69.4688, 224.1531) -> (74.9652, 213.2153)
  curve K25 (67.2512, 226.458) -> (69.4688, 224.1531)
  curve K26 (61.5696, 231.3138) -> (67.2512, 226.458)
  curve K27 (57.377, 234.6711) -> (61.5696, 231.3138)
  curve K28 (52.0556, 237.2628) -> (57.377, 234.6711)
  curve K29 (51.4313, 237.5413) -> (52.0556, 237.2628)
  curve K30 (50.8, 237.7999) -> (51.4313, 237.5413)
  line L2 (-50.8, 317.5) -> (-50.8, 237.8015)
  line L3 (50.8, 317.5) -> (50.8, 237.7999)
  line L4 (-19.0713, 6.7501) -> (-19.0713, 6.7501)
  curve K31 (82.9821, 124.1958) -> (40.1509, 7.3012)
  curve K32 (41.8198, 7.6176) -> (40.1509, 7.3012)
  curve K33 (43.2113, 8.0663) -> (41.8198, 7.6176)
  curve K34 (47.0139, 9.2854) -> (43.2113, 8.0663)
  curve K35 (47.3314, 9.3805) -> (47.0139, 9.2854)
  curve K36 (50.1192, 10.3272) -> (47.3314, 9.3805)
  curve K37 (51.833, 11.0085) -> (50.1192, 10.3272)
  curve K38 (57.8313, 14.1895) -> (51.833, 11.0085)
  curve K39 (61.4491, 17.0488) -> (57.8313, 14.1895)
  curve K40 (66.8203, 21.5867) -> (61.4491, 17.0488)
  curve K41 (68.5372, 23.5528) -> (66.8203, 21.5867)
  curve K42 (71.2201, 27.8971) -> (68.5372, 23.5528)
  curve K43 (74.7424, 33.8984) -> (71.2201, 27.8971)
  curve K44 (78.2342, 44.8406) -> (74.7424, 33.8984)
  curve K45 (79.6792, 50.3463) -> (78.2342, 44.8406)
  curve K46 (81.3558, 63.5576) -> (79.6792, 50.3463)
  curve K47 (81.6386, 70.4415) -> (81.3558, 63.5576)
  curve K48 (82.4897, 96.2198) -> (81.6386, 70.4415)
  curve K49 (82.9814, 112.3523) -> (82.4897, 96.2198)
  curve K50 (82.9821, 124.1958) -> (82.9814, 112.3523)
  curve K51 (-40.1501, 7.301) -> (-82.9821, 124.1958)
  curve K52 (-82.9813, 110.5256) -> (-82.9821, 124.1958)
  curve K53 (-82.2545, 88.8594) -> (-82.9813, 110.5256)
  curve K54 (-81.6277, 70.519) -> (-82.2545, 88.8594)
  curve K55 (-81.3572, 64.3441) -> (-81.6277, 70.519)
  curve K56 (-79.4149, 46.8924) -> (-81.3572, 64.3441)
  curve K57 (-76.5204, 38.9768) -> (-79.4149, 46.8924)
  curve K58 (-73.5142, 32.2947) -> (-76.5204, 38.9768)
  curve K59 (-72.5556, 30.3818) -> (-73.5142, 32.2947)
  curve K60 (-69.7914, 25.3691) -> (-72.5556, 30.3818)
  curve K61 (-68.3824, 23.4028) -> (-69.7914, 25.3691)
  curve K62 (-64.5419, 19.5456) -> (-68.3824, 23.4028)
  curve K63 (-62.3002, 17.7646) -> (-64.5419, 19.5456)
  curve K64 (-53.6583, 11.1976) -> (-62.3002, 17.7646)
  curve K65 (-49.6968, 10.1396) -> (-53.6583, 11.1976)
  curve K66 (-43.4141, 8.1331) -> (-49.6968, 10.1396)
  curve K67 (-41.9704, 7.6516) -> (-43.4141, 8.1331)
  curve K68 (-40.1963, 7.3098) -> (-41.9704, 7.6516)
  curve K69 (-40.1732, 7.3054) -> (-40.1963, 7.3098)
  curve K70 (-40.1501, 7.301) -> (-40.1732, 7.3054)
  line L5 (-82.9821, 124.1958) -> (-82.9821, 124.2212)
  line L6 (82.9821, 124.2212) -> (82.9821, 124.1958)
  line L7 (0, 317.5) -> (-50.8, 317.5)
  line L8 (7.2015, 3.048) -> (0, 3.048)
  line L9 (0, 3.048) -> (-7.2015, 3.048)
  arc A1 centre (0, 188.595) radius 185.6867 clockwise from (-7.2015, 3.048) to (-40.1502, 7.301)
  arc A2 centre (0, 188.595) radius 185.6867 clockwise from (40.151, 7.3012) to (7.2015, 3.048)
  point P38 (-40.1502, 7.301)
  point P43 (40.1509, 7.3012)
  point P62 (-40.1501, 7.301)
  point P81 (40.151, 7.3012)
  point P84 (0, 3.048)
  vertical L1
  horizontal L4
  coincident P38 K51
  symmetric L1 A1 A2
  coincident A2 P43
  coincident A1 P62
  coincident K31 P81
  perpendicular L2 L7
  horizontal L8
  coincident L1 P84
  horizontal L9
revolve "Revolve1" sketch "Sketch1" AlongAngle 360
shell "Shell1" innerThickness 3.81
fillet "Fillet1" radius 6.35 bodies "Balon v3"
offset_faces "OffsetFaces1" distance -50.8
move "Move1"
move "Move2"
component_from_bodies "Body->Comp1"
component_from_bodies "Body->Comp2"
sketch "Sketch2" plane through (0, 0, 0) normal (0, 1, 0) x axis (1, 0, 0)
  line L1 (-85.5221, 124.2212) -> (-85.5221, 124.1961)
  curve K1 (-58.9057, 236.4383) -> (-50.8, 241.7989)
  curve K2 (-50.8, 241.554) -> (-50.8, 241.7989)
  curve K3 (-50.904, 240.933) -> (-50.8, 241.554)
  curve K4 (-51.2936, 240.2837) -> (-50.904, 240.933)
  curve K5 (-51.734, 239.7561) -> (-51.2936, 240.2837)
  curve K6 (-53.328, 238.5038) -> (-51.734, 239.7561)
  curve K7 (-54.0892, 238.1997) -> (-53.328, 238.5038)
  curve K8 (-58.9057, 236.4383) -> (-54.0892, 238.1997)
  curve K9 (-89.3309, 124.2212) -> (-58.9057, 236.4383)
  curve K10 (-62.6336, 234.9735) -> (-58.9057, 236.4383)
  curve K11 (-65.581, 233.1032) -> (-62.6336, 234.9735)
  curve K12 (-73.0224, 227.0019) -> (-65.581, 233.1032)
  curve K13 (-74.8981, 224.836) -> (-73.0224, 227.0019)
  curve K14 (-78.1104, 219.6097) -> (-74.8981, 224.836)
  curve K15 (-80.2663, 215.561) -> (-78.1104, 219.6097)
  curve K16 (-84.0943, 205.8277) -> (-80.2663, 215.561)
  curve K17 (-85.4655, 200.1154) -> (-84.0943, 205.8277)
  curve K18 (-87.4092, 188.5789) -> (-85.4655, 200.1154)
  curve K19 (-87.7349, 182.3889) -> (-87.4092, 188.5789)
  curve K20 (-88.4233, 165.9645) -> (-87.7349, 182.3889)
  curve K21 (-89.328, 138.6964) -> (-88.4233, 165.9645)
  curve K22 (-89.3309, 124.2212) -> (-89.328, 138.6964)
  line L2 (-89.3309, 124.1958) -> (-89.3309, 124.2212)
  curve K23 (-46.5001, 7.301) -> (-89.3309, 124.1958)
  curve K24 (-89.3314, 112.4293) -> (-89.3309, 124.1958)
  curve K25 (-88.8181, 95.3068) -> (-89.3314, 112.4293)
  curve K26 (-88.346, 81.2892) -> (-88.8181, 95.3068)
  curve K27 (-88.0298, 70.4902) -> (-88.346, 81.2892)
  curve K28 (-87.1514, 58.328) -> (-88.0298, 70.4902)
  curve K29 (-86.3326, 50.6119) -> (-87.1514, 58.328)
  curve K30 (-81.0932, 33.6688) -> (-86.3326, 50.6119)
  curve K31 (-77.3163, 27.4309) -> (-81.0932, 33.6688)
  curve K32 (-74.8955, 23.6666) -> (-77.3163, 27.4309)
  curve K33 (-73.5108, 22.0741) -> (-74.8955, 23.6666)
  curve K34 (-70.2346, 19.0457) -> (-73.5108, 22.0741)
  curve K35 (-64.8094, 14.3548) -> (-70.2346, 19.0457)
  curve K36 (-56.6696, 10.3041) -> (-64.8094, 14.3548)
  curve K37 (-54.0053, 9.483) -> (-56.6696, 10.3041)
  curve K38 (-49.1487, 7.9411) -> (-54.0053, 9.483)
  curve K39 (-48.3482, 7.6526) -> (-49.1487, 7.9411)
  curve K40 (-46.5001, 7.301) -> (-48.3482, 7.6526)
  line L3 (0, 266.7) -> (0, 0)
  line L4 (0, 3.048) -> (-7.7894, 3.048)
  line L5 (-50.8, 266.7) -> (-50.8, 241.7989)
  line L6 (0, 266.7) -> (-50.8, 266.7)
  arc A1 centre (-6.9779, 188.7329) radius 185.6867 clockwise from (-7.7894, 3.048) to (-46.5001, 7.301)
  point P1 (0, 0)
  point P44 (0, 0)
  point P46 (0, 3.048)
  point P5 (-50.8, 241.554)
  point P49 (0, 266.7)
  coincident P1 P44
  coincident L3 P46
  coincident P5 L5
  coincident L3 P49
revolve "Revolve2" sketch "Sketch2" AlongAngle 360 bodies "Balon v3"
shell "Shell2" innerThickness 3.81
component_from_bodies "Body->Comp3"
remove_instance "RemoveInstance1"
remove_instance "RemoveInstance2"
sketch "Sketch1" plane through (0, 0, 0) normal (0, 1, 0) x axis (1, 0, 0)
  line L1 (-6.35, 3.048) -> (-14.1394, 3.048)
  curve K1 (-52.8501, 7.301) -> (-95.6809, 124.1958)
  curve K2 (-95.6814, 112.4293) -> (-95.6809, 124.1958)
  curve K3 (-95.1681, 95.3068) -> (-95.6814, 112.4293)
  curve K4 (-94.696, 81.2892) -> (-95.1681, 95.3068)
  curve K5 (-94.3798, 70.4902) -> (-94.696, 81.2892)
  curve K6 (-93.5014, 58.328) -> (-94.3798, 70.4902)
  curve K7 (-92.6826, 50.6119) -> (-93.5014, 58.328)
  curve K8 (-87.4432, 33.6688) -> (-92.6826, 50.6119)
  curve K9 (-83.6663, 27.4309) -> (-87.4432, 33.6688)
  curve K10 (-81.2455, 23.6666) -> (-83.6663, 27.4309)
  curve K11 (-79.8608, 22.0741) -> (-81.2455, 23.6666)
  curve K12 (-76.5846, 19.0457) -> (-79.8608, 22.0741)
  curve K13 (-71.12, 13.97) -> (-76.5846, 19.0457)
  curve K14 (-62.23, 10.16) -> (-71.12, 13.97)
  curve K15 (-60.3553, 9.483) -> (-62.23, 10.16)
  curve K16 (-55.4987, 7.9411) -> (-60.3553, 9.483)
  curve K17 (-54.6982, 7.6526) -> (-55.4987, 7.9411)
  curve K18 (-52.8501, 7.301) -> (-54.6982, 7.6526)
  line L2 (-95.6809, 124.1958) -> (-95.6809, 124.2212)
  line L3 (0, 266.7) -> (0, 0)
  line L4 (0, 3.048) -> (-6.35, 3.048)
  line L5 (-95.6809, 124.2466) -> (-95.6809, 124.2212)
  line L6 (-50.8, 266.7) -> (-50.8, 241.7989)
  line L7 (0, 266.7) -> (-50.8, 266.7)
  curve K19 (-71.6837, 232.5587) -> (-50.8, 241.7989)
  curve K20 (-50.8, 237.8015) -> (-50.8, 241.7989)
  curve K21 (-53.6019, 236.5654) -> (-50.8, 237.8015)
  curve K22 (-59.7861, 236.0598) -> (-53.6019, 236.5654)
  curve K23 (-64.4375, 235.2772) -> (-59.7861, 236.0598)
  curve K24 (-69.8917, 233.4707) -> (-64.4375, 235.2772)
  curve K25 (-71.6837, 232.5587) -> (-69.8917, 233.4707)
  curve K26 (-71.6837, 232.5587) -> (-95.6809, 124.2466)
  curve K27 (-95.6814, 136.0132) -> (-95.6809, 124.2466)
  curve K28 (-95.1681, 153.1357) -> (-95.6814, 136.0132)
  curve K29 (-94.696, 167.1533) -> (-95.1681, 153.1357)
  curve K30 (-94.3798, 177.9523) -> (-94.696, 167.1533)
  curve K31 (-93.5014, 190.1145) -> (-94.3798, 177.9523)
  curve K32 (-92.6826, 197.8306) -> (-93.5014, 190.1145)
  curve K33 (-87.4432, 214.7737) -> (-92.6826, 197.8306)
  curve K34 (-83.6663, 221.0115) -> (-87.4432, 214.7737)
  curve K35 (-81.2455, 224.7759) -> (-83.6663, 221.0115)
  curve K36 (-79.8608, 226.3684) -> (-81.2455, 224.7759)
  curve K37 (-77.083, 228.9361) -> (-79.8608, 226.3684)
  curve K38 (-75.5537, 230.2778) -> (-77.083, 228.9361)
  curve K39 (-71.6837, 232.5587) -> (-75.5537, 230.2778)
  curve K40 (-50.8, 244.8458) -> (-50.8, 244.8469)
  curve K41 (-50.8, 244.8465) -> (-50.8, 244.8469)
  curve K42 (-50.8, 244.8462) -> (-50.8, 244.8465)
  curve K43 (-50.8, 244.8458) -> (-50.8, 244.8462)
  arc A1 centre (-13.3279, 188.7329) radius 185.6867 clockwise from (-14.1394, 3.048) to (-52.8501, 7.301)
  point P26 (0, 3.048)
  point P33 (-50.8, 237.8015)
  point P35 (-50.8, 237.8015)
  point P40 (-71.6837, 232.5587)
  point P53 (-50.8, 244.8458)
  coincident L3 P26
  perpendicular L3 L4
  coincident P33 P35
  coincident K19 P40
  coincident L6 P53
sketch "Sketch2" plane through (0, 0, 0) normal (0, 1, 0) x axis (1, 0, 0)
  line L1 (-95.6809, 124.1958) -> (-95.6809, 124.2212)
  line L2 (0, 266.7) -> (-50.8, 266.7)
  curve K1 (-58.9317, 239.3909) -> (-50.8, 244.8469)
  curve K2 (-50.8, 244.602) -> (-50.8, 244.8469)
  curve K3 (-50.904, 243.981) -> (-50.8, 244.602)
  curve K4 (-51.2936, 243.3317) -> (-50.904, 243.981)
  curve K5 (-51.734, 242.8041) -> (-51.2936, 243.3317)
  curve K6 (-53.328, 241.5518) -> (-51.734, 242.8041)
  curve K7 (-54.0892, 241.2477) -> (-53.328, 241.5518)
  curve K8 (-58.9317, 239.3909) -> (-54.0892, 241.2477)
  line L3 (-50.8, 266.7) -> (-50.8, 244.8458)
  curve K9 (-52.8501, 7.301) -> (-95.6809, 124.1958)
  curve K10 (-95.6814, 112.4293) -> (-95.6809, 124.1958)
  curve K11 (-95.1681, 95.3068) -> (-95.6814, 112.4293)
  curve K12 (-94.696, 81.2892) -> (-95.1681, 95.3068)
  curve K13 (-94.3798, 70.4902) -> (-94.696, 81.2892)
  curve K14 (-93.5014, 58.328) -> (-94.3798, 70.4902)
  curve K15 (-92.6826, 50.6119) -> (-93.5014, 58.328)
  curve K16 (-87.4432, 33.6688) -> (-92.6826, 50.6119)
  curve K17 (-83.6663, 27.4309) -> (-87.4432, 33.6688)
  curve K18 (-81.2455, 23.6666) -> (-83.6663, 27.4309)
  curve K19 (-79.8608, 22.0741) -> (-81.2455, 23.6666)
  curve K20 (-76.5846, 19.0457) -> (-79.8608, 22.0741)
  curve K21 (-73.7599, 16.6033) -> (-76.5846, 19.0457)
  curve K22 (-65.532, 11.7145) -> (-73.7599, 16.6033)
  curve K23 (-60.3553, 9.483) -> (-65.532, 11.7145)
  curve K24 (-55.4987, 7.9411) -> (-60.3553, 9.483)
  curve K25 (-54.6982, 7.6526) -> (-55.4987, 7.9411)
  curve K26 (-52.8501, 7.301) -> (-54.6982, 7.6526)
  line L4 (-95.6809, 124.2466) -> (-95.6809, 124.2212)
  line L5 (0, 3.048) -> (-6.35, 3.048)
  line L6 (-6.35, 3.048) -> (-14.1394, 3.048)
  curve K27 (-58.9317, 239.3909) -> (-95.6809, 124.2466)
  curve K28 (-95.6814, 136.0132) -> (-95.6809, 124.2466)
  curve K29 (-95.1681, 153.1357) -> (-95.6814, 136.0132)
  curve K30 (-94.696, 167.1533) -> (-95.1681, 153.1357)
  curve K31 (-94.3798, 177.9523) -> (-94.696, 167.1533)
  curve K32 (-93.5014, 190.1145) -> (-94.3798, 177.9523)
  curve K33 (-92.6826, 197.8306) -> (-93.5014, 190.1145)
  curve K34 (-87.4432, 214.7737) -> (-92.6826, 197.8306)
  curve K35 (-83.6663, 221.0115) -> (-87.4432, 214.7737)
  curve K36 (-81.2455, 224.7759) -> (-83.6663, 221.0115)
  curve K37 (-79.8608, 226.3684) -> (-81.2455, 224.7759)
  curve K38 (-76.5846, 229.3968) -> (-79.8608, 226.3684)
  curve K39 (-73.7599, 231.8391) -> (-76.5846, 229.3968)
  curve K40 (-65.833, 236.5491) -> (-73.7599, 231.8391)
  curve K41 (-61.4585, 238.4785) -> (-65.833, 236.5491)
  curve K42 (-58.9317, 239.3909) -> (-61.4585, 238.4785)
  line L7 (0, 3.048) -> (0, 266.7)
  arc A1 centre (-13.3279, 188.7329) radius 185.6867 clockwise from (-14.1394, 3.048) to (-52.8501, 7.301)
  point P52 (-50.8, 244.8458)
  coincident K1 P52
  perpendicular L5 L7
revolve "Revolve1" sketch "Sketch1" AlongAngle 360 bodies "Balon v3.3"
shell "Shell1" innerThickness 3.81
revolve "Revolve2" sketch "Sketch2" AlongAngle 360 bodies "Balon v3.2"
shell "Shell2" innerThickness 3.81
component_from_bodies "Body->Comp1"
component_from_bodies "Body->Comp2"
position "Position1"
remove_instance "RemoveInstance1" bodies "Balon v3"
remove_instance "RemoveInstance2"
move "Move1"
position "Position2" bodies "Balon v3"
sketch "Sketch3" plane through (0, 0, 0) normal (0, 1, 0) x axis (1, 0, 0)
  line L1 (0, 50.8) -> (0, -304.8)
  line L2 (127, 50.8) -> (127, -304.8)
  line L3 (-127, 50.8) -> (-127, -304.8)
  line L4 (139.7, 25.4) -> (-139.7, 25.4)
  line L5 (139.7, -292.1) -> (-139.7, -292.1)
  line L6 (95.25, 50.8) -> (95.25, -304.8)
  vertical L1
  dimension "d6" = 127
  dimension "d12" = -127
  dimension "d17" distance L4 L5 = 317.5
  dimension "d18" = 95.25
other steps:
base_feature "Base Feature1" bodies "Balon v3.3"
base_feature "Base Feature1" bodies "Balon v3.2"
base_feature "Base Feature1" bodies "Balon"
base_feature "Base Feature1" bodies "Balon v3"
base_feature "Base Feature1" bodies "Balon v2"
create_component "CreateComponent1"
remove_body "RemoveBody1"
create_component "CreateComponent2"
remove_body "RemoveBody2"
create_component "CreateComponent3"
remove_body "RemoveBody3" bodies "Balon v3"
create_component "CreateComponent1"
create_component "CreateComponent2"
remove_body "RemoveBody1" bodies "Balon v3"
create_component "CreateComponent3"
remove_body "RemoveBody2" bodies "Balon v3"
named bodies: "Balon", "Balon v2", "Balon v3", "Balon v3.3", "Balon v3.2"

design "Rubber Grommet"
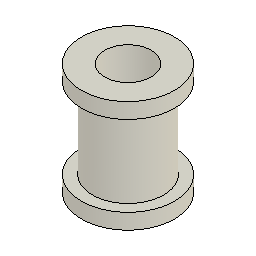
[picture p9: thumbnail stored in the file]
sketch "Sketch1" plane through (0, 0, 0) normal (0, 1, 0) x axis (1, 0, 0)
  line L1 (0, 3.048) -> (0, -12.7)
  line L2 (5.842, 0.508) -> (5.842, -12.7)
  line L3 (3.81, 3.048) -> (3.81, -15.24)
  line L4 (7.62, -12.7) -> (7.62, -15.24)
  line L5 (7.62, 3.048) -> (7.62, 0.508)
  line L6 (7.62, 0.508) -> (5.842, 0.508)
  line L7 (7.62, -12.7) -> (5.842, -12.7)
  line L8 (7.62, -15.24) -> (3.81, -15.24)
  line L9 (7.62, 3.048) -> (3.81, 3.048)
  vertical L1
  collinear L4 L5
revolve "Revolve1" sketch "Sketch1" AlongAngle 360 bodies "Rubber Grommet"
component_from_bodies "Body->Comp"
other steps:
base_feature "Base Feature" bodies "Rubber Grommet"
create_component "CreateComponent1"
remove_body "RemoveBody1"
named bodies: "Rubber Grommet"

design "Trove - TL"
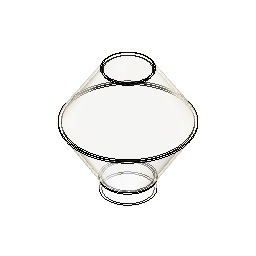
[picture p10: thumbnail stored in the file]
derived_base_feature "Derived Base Feature" bodies "Trove"
hole "Hole1" HoleDepth 88.9 HoleDiameter 44.45 TipAngle 118
sketch "Sketch1" plane through (0, 0, 0) normal (1, 0, 0) x axis (0, 1, 0)
  line L1 (0, 243.0601) -> (0, 247.8226)
  line L2 (-50.8, -12.7122) -> (-50.8, 10.9447)
  line L3 (0, -25.4) -> (0, 243.0601)
  line L4 (-46.0375, -12.7122) -> (-50.8, -12.7122)
  line L5 (-46.0375, -12.7122) -> (-46.0375, 12.3043)
  line L6 (-45.9716, 247.8226) -> (0, 247.8226)
  line L7 (-43.3841, 243.0601) -> (0, 243.0601)
  line L8 (-122.8321, 128.6352) -> (-51.757, 14.2971)
  line L9 (-117.1907, 128.5808) -> (-46.9945, 15.6567)
  line L10 (-48.6353, 246.3754) -> (-122.7993, 132.0392)
  line L11 (-46.0478, 241.6129) -> (-117.1579, 131.9848)
  arc A1 centre (-57.15, 10.9447) radius 6.35 clockwise from (-51.757, 14.2971) to (-50.8, 10.9447)
  arc A2 centre (-52.3875, 12.3043) radius 6.35 clockwise from (-46.9945, 15.6567) to (-46.0375, 12.3043)
  arc A3 centre (-114.4942, 130.257) radius 3.175 between (-117.1579, 131.9848) and (-117.1907, 128.5808)
  arc A4 centre (-120.1356, 130.3114) radius 3.175 between (-122.7993, 132.0392) and (-122.8321, 128.6352)
  arc A5 centre (-45.9716, 244.6476) radius 3.175 between (-45.9716, 247.8226) and (-48.6353, 246.3754)
  arc A6 centre (-43.3841, 239.8851) radius 3.175 clockwise from (-46.0478, 241.6129) to (-43.3841, 243.0601)
  point P3 (0, 247.8226)
  point P4 (0, 243.0601)
  vertical L1
  vertical L3
  tangent L5 A2
  perpendicular L1 L6
  perpendicular L1 L7
  tangent L11 A3
  tangent L9 A3
  tangent L10 A4
  tangent L8 A4
  equal A3 A4
  tangent L6 A5
  tangent L10 A5
  tangent L11 A6
  tangent L7 A6
  dimension "d8" distance P3 P4 = 4.7625
  dimension "d11" radius A2 = 6.35
  dimension "d15" radius A3 = 3.175
  dimension "d16" radius A5 = 3.175
  dimension "d17" radius A6 = 3.175
revolve "Revolve1" sketch "Sketch1" AlongAngle 180 bodies "Trove - TL"
revolve "Revolve2" sketch "Sketch1" AlongAngle -180
component_from_bodies "Body->Comp"
remove_body "RemoveBody2"
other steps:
base_feature "Base Feature" bodies "Trove - TL"
create_component "CreateComponent1"
remove_body "RemoveBody1"
named bodies: "Trove", "Trove - TL"

design "T9-5In"
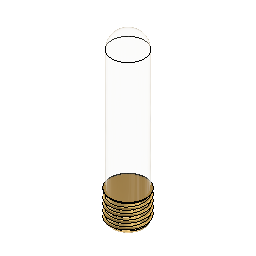
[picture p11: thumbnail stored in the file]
sketch "Sketch1" plane through (0, 0, 0) normal (0, 1, 0) x axis (1, 0, 0)
  line L1 (0, 0) -> (0, -127)
  line L2 (12.7, -127) -> (-12.7, -127)
  line L3 (12.7, -12.7) -> (12.7, -127)
  line L4 (-12.7, -127) -> (-12.7, -12.7)
  arc A1 centre (0, -12.7) radius 12.7 clockwise from (-12.7, -12.7) to (12.7, -12.7)
  point P1 (0, 0)
  point P3 (0, 0)
  coincident P1 P3
  vertical L1
  horizontal L2
  vertical L3
  vertical L4
revolve "Revolve1" sketch "Sketch1" AlongAngle 360 bodies "BU-T10-5-LED-120V"
derived_base_feature "Derived Base Feature" bodies "E26 Base"
move "Move1"
component_from_bodies "Body->Comp"
copy_paste "CutPaste"
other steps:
base_feature "Base Feature" bodies "BU-T10-5-LED-120V"
create_component "CreateComponent1"
create_component "CreateComponent2"
remove_body "RemoveBody1"
remove_instance "RemoveInstance1"
named bodies: "BU-T10-5-LED-120V", "E26 Base"
